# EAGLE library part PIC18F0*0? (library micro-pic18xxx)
High Performance 8pin Microcontrollers
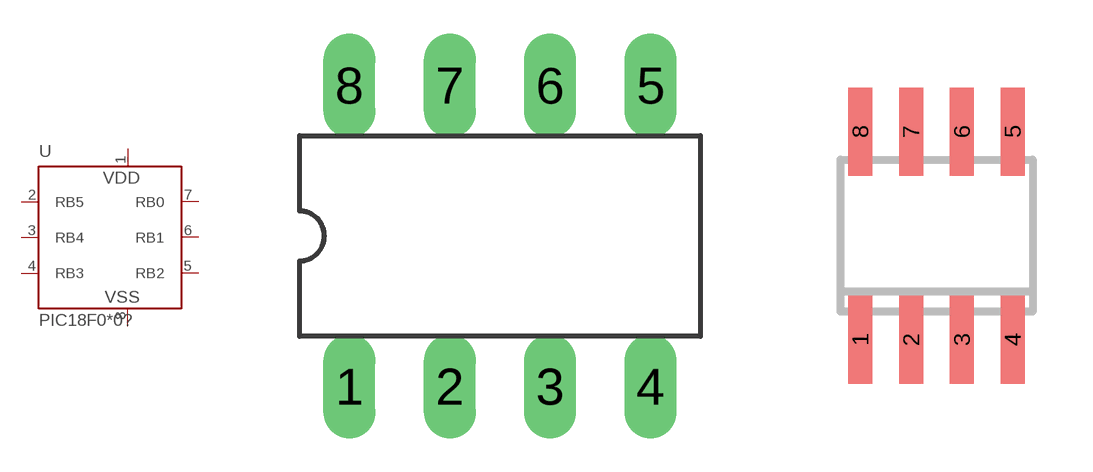
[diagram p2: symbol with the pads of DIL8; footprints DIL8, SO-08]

Designator prefix -

## PIC18F010P, PIC18F020P  [DIL8]
1  VDD  pwr
2  RB5  in
3  RB4  in
4  RB3  in
5  RB2  hiz
6  RB1  out
7  RB0  in
8  VSS  pwr

## PIC18F010SN, PIC18F020SN  [SO-08]
Pads as for DIL8

## Footprint DIL8 (pad centres in mm)
DIL package type P
drill 0.813 long: 1 -3.81,-3.81; 2 -1.27,-3.81; 3 1.27,-3.81; 4 3.81,-3.81; 5 3.81,3.81; 6 1.27,3.81; 7 -1.27,3.81; 8 -3.81,3.81

## Footprint SO-08 (pad centres in mm)
Small Outline Narrow Plastic Gull Wing 150-mil body package type SN
smd 0.6 x 2.2: 1 -1.905,-2.6; 2 -0.635,-2.6; 3 0.635,-2.6; 4 1.905,-2.6; 5 1.905,2.6; 6 0.635,2.6; 7 -0.635,2.6; 8 -1.905,2.6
